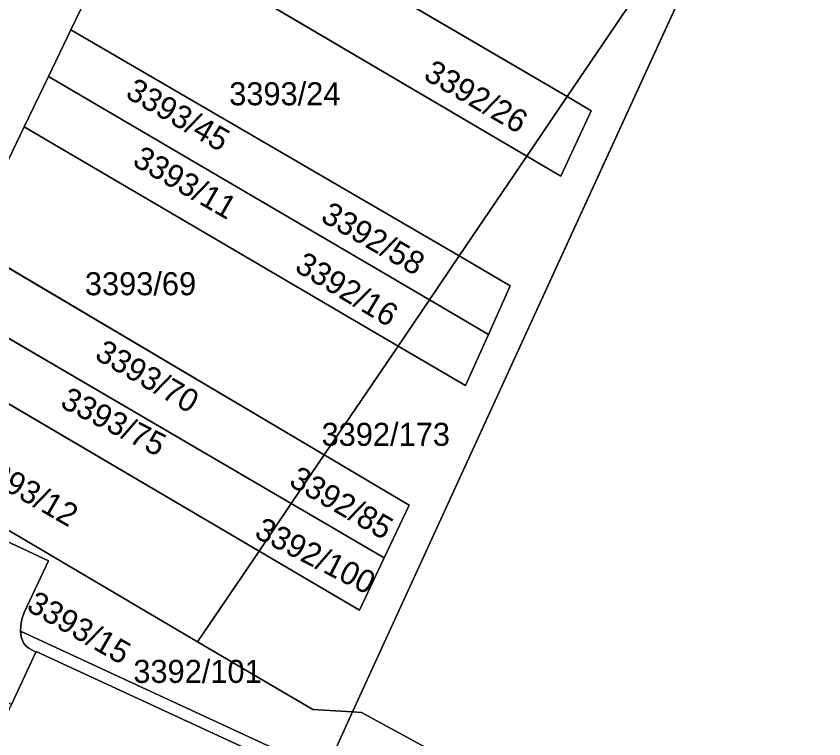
# Model space of a CAD drawing. Extents: x -262715 to -259381, y -1237238 to -1231182.
# Drawn here: x -261371.9 to -261301.7, y -1235929.8 to -1235867.1 of the extents above; entities that cross this region are included whole.
import ezdxf

# ---------------------------------------------------------------- set-up
doc = ezdxf.new("R2010")
doc.units = 0
for name, color, linetype in [('body_kn', 7, 'Continuous'), ('kladpar_druhypozemkov', 7, 'Continuous'), ('kladpar_hranice', 7, 'Continuous'), ('kladpar_parcelnecisla', 7, 'Continuous'), ('kladpar_plochy', 7, 'Continuous'), ('kladpar_sipky', 7, 'Continuous'), ('zuob_linie', 7, 'Continuous'), ('zuob_plochy', 7, 'Continuous')]:
    doc.layers.add(name, color=color, linetype=linetype)

msp = doc.modelspace()

# ---------------------------------------------------------------- linework, layer by layer
at = {"layer": 'body_kn'}
for p, q in [((-261367.16, -1235868.27), (-261367.16, -1235868.27)), ((-261367.16, -1235868.27), (-261367.16, -1235868.27)), ((-261369.1, -1235872.3), (-261369.1, -1235872.3)), ((-261369.1, -1235872.3), (-261369.1, -1235872.3)), ((-261324.01, -1235874.06), (-261324.01, -1235874.06)), ((-261324.01, -1235874.06), (-261324.01, -1235874.06)), ((-261321.93, -1235875.28), (-261321.93, -1235875.28)), ((-261371.21, -1235876.69), (-261371.21, -1235876.69)), ((-261371.21, -1235876.69), (-261371.21, -1235876.69)), ((-261327.53, -1235879.24), (-261327.53, -1235879.24)), ((-261327.53, -1235879.24), (-261327.53, -1235879.24)), ((-261324.58, -1235880.98), (-261324.58, -1235880.98)), ((-261333.4, -1235887.9), (-261333.4, -1235887.9)), ((-261333.4, -1235887.9), (-261333.4, -1235887.9)), ((-261328.96, -1235890.48), (-261328.96, -1235890.48)), ((-261335.99, -1235891.71), (-261335.99, -1235891.71)), ((-261335.99, -1235891.71), (-261335.99, -1235891.71)), ((-261330.85, -1235894.72), (-261330.85, -1235894.72)), ((-261330.85, -1235894.72), (-261330.85, -1235894.72)), ((-261338.71, -1235895.72), (-261338.71, -1235895.72)), ((-261338.71, -1235895.72), (-261338.71, -1235895.72)), ((-261332.86, -1235899.14), (-261332.86, -1235899.14)), ((-261332.86, -1235899.14), (-261332.86, -1235899.14)), ((-261345.13, -1235905.18), (-261345.13, -1235905.18)), ((-261345.13, -1235905.18), (-261345.13, -1235905.18)), ((-261348, -1235909.41), (-261348, -1235909.41)), ((-261337.75, -1235909.55), (-261337.75, -1235909.55)), ((-261350.79, -1235913.53), (-261350.79, -1235913.53)), ((-261350.79, -1235913.53), (-261350.79, -1235913.53)), ((-261369.08, -1235914.38), (-261369.08, -1235914.38)), ((-261339.93, -1235914.13), (-261339.93, -1235914.13)), ((-261339.93, -1235914.13), (-261339.93, -1235914.13)), ((-261342.06, -1235918.65), (-261342.06, -1235918.65)), ((-261371.41, -1235919.44), (-261371.41, -1235919.44)), ((-261371.21, -1235918.88), (-261371.21, -1235918.88)), ((-261371.49, -1235920.03), (-261371.49, -1235920.03)), ((-261371.51, -1235920.48), (-261371.51, -1235920.48)), ((-261371.45, -1235921.01), (-261371.45, -1235921.01)), ((-261371.22, -1235921.56), (-261371.22, -1235921.56)), ((-261356.13, -1235921.41), (-261356.13, -1235921.41)), ((-261356.13, -1235921.41), (-261356.13, -1235921.41)), ((-261371.03, -1235921.8), (-261371.03, -1235921.8)), ((-261370.81, -1235921.97), (-261370.81, -1235921.97)), ((-261370.19, -1235922.32), (-261370.19, -1235922.32)), ((-261370.16, -1235922.25), (-261370.16, -1235922.25)), ((-261346.13, -1235927.3), (-261346.13, -1235927.3)), ((-261342.66, -1235927.5), (-261342.66, -1235927.5)), ((-261342.66, -1235927.5), (-261342.66, -1235927.5)), ((-261341.89, -1235927.54), (-261341.89, -1235927.54)), ((-261341.89, -1235927.54), (-261341.89, -1235927.54))]:
    msp.add_line(p, q, dxfattribs=at)
at = {"layer": 'kladpar_druhypozemkov'}
for p, q in [((-261346.94, -1235872.59), (-261346.94, -1235872.59)), ((-261364.07, -1235873.52), (-261364.07, -1235873.52)), ((-261324.34, -1235877.36), (-261324.34, -1235877.36)), ((-261365.48, -1235878.07), (-261365.48, -1235878.07)), ((-261361.27, -1235889.66), (-261361.27, -1235889.66)), ((-261333.24, -1235892.93), (-261333.24, -1235892.93)), ((-261366.82, -1235896.06), (-261366.82, -1235896.06)), ((-261333.79, -1235898.01), (-261333.79, -1235898.01)), ((-261368.44, -1235900.45), (-261368.44, -1235900.45)), ((-261339.63, -1235902.21), (-261339.63, -1235902.21)), ((-261369.42, -1235907.68), (-261369.42, -1235907.68)), ((-261341.83, -1235909.49), (-261341.83, -1235909.49)), ((-261344.46, -1235913.47), (-261344.46, -1235913.47)), ((-261365.41, -1235919.57), (-261365.41, -1235919.57)), ((-261358.61, -1235927.02), (-261358.61, -1235927.02))]:
    msp.add_line(p, q, dxfattribs=at)
at = {"layer": 'kladpar_hranice'}
for p, q in [((-261305.98, -1235847.48), (-261342.66, -1235927.5)), ((-261324.01, -1235874.06), (-261305.98, -1235847.48)), ((-261360.53, -1235852.69), (-261324.01, -1235874.06)), ((-261324.01, -1235874.06), (-261360.53, -1235852.69)), ((-261362.88, -1235858.42), (-261327.53, -1235879.24)), ((-261369.1, -1235872.3), (-261367.16, -1235868.27)), ((-261333.4, -1235887.9), (-261367.16, -1235868.27)), ((-261367.16, -1235868.27), (-261333.4, -1235887.9)), ((-261371.21, -1235876.69), (-261369.1, -1235872.3)), ((-261335.99, -1235891.71), (-261369.1, -1235872.3)), ((-261369.1, -1235872.3), (-261335.99, -1235891.71)), ((-261327.53, -1235879.24), (-261324.01, -1235874.06)), ((-261376.11, -1235886.85), (-261371.21, -1235876.69)), ((-261338.71, -1235895.72), (-261371.21, -1235876.69)), ((-261371.21, -1235876.69), (-261338.71, -1235895.72)), ((-261327.53, -1235879.24), (-261333.4, -1235887.9)), ((-261333.4, -1235887.9), (-261327.53, -1235879.24)), ((-261376.11, -1235886.85), (-261345.13, -1235905.18)), ((-261333.4, -1235887.9), (-261335.99, -1235891.71)), ((-261348, -1235909.41), (-261378.39, -1235891.64)), ((-261378.39, -1235891.64), (-261348, -1235909.41)), ((-261335.99, -1235891.71), (-261338.71, -1235895.72)), ((-261350.79, -1235913.53), (-261380.48, -1235896.1)), ((-261380.48, -1235896.1), (-261350.79, -1235913.53)), ((-261345.13, -1235905.18), (-261348, -1235909.41)), ((-261348, -1235909.41), (-261345.13, -1235905.18)), ((-261348, -1235909.41), (-261350.79, -1235913.53)), ((-261350.79, -1235913.53), (-261348, -1235909.41)), ((-261348, -1235909.41), (-261339.93, -1235914.13)), ((-261350.79, -1235913.53), (-261356.13, -1235921.41)), ((-261356.13, -1235921.41), (-261350.79, -1235913.53)), ((-261342.66, -1235927.5), (-261341.89, -1235927.54))]:
    msp.add_line(p, q, dxfattribs=at)
for points in [[(-261319.46, -1235828.94), (-261311.13, -1235840.39), (-261305.98, -1235847.48), (-261324.01, -1235874.06)], [(-261386.5, -1236069.65), (-261377.1, -1236074.79), (-261372.8, -1236072.22), (-261361.27, -1236060.35), (-261345.62, -1236044.25), (-261341.5, -1236035.34), (-261337.33, -1236026.34), (-261329.78, -1236010.04), (-261326.26, -1236002.43), (-261322.63, -1235994.6), (-261319.1, -1235986.99), (-261315.58, -1235979.39), (-261312.39, -1235972.5), (-261308.86, -1235964.89), (-261301.71, -1235949.44), (-261323.71, -1235937.45), (-261341.89, -1235927.54), (-261342.66, -1235927.5), (-261305.98, -1235847.48)], [(-261367.16, -1235868.27), (-261365.45, -1235864.71), (-261362.88, -1235858.42)], [(-261324.01, -1235874.06), (-261327.53, -1235879.24), (-261362.88, -1235858.42)], [(-261365.45, -1235864.71), (-261367.16, -1235868.27), (-261369.1, -1235872.3), (-261371.21, -1235876.69), (-261376.11, -1235886.85)], [(-261324.01, -1235874.06), (-261321.93, -1235875.28), (-261324.58, -1235880.98), (-261327.53, -1235879.24)], [(-261327.53, -1235879.24), (-261324.58, -1235880.98), (-261321.93, -1235875.28), (-261324.01, -1235874.06)], [(-261338.71, -1235895.72), (-261345.13, -1235905.18), (-261376.11, -1235886.85)], [(-261330.85, -1235894.72), (-261335.99, -1235891.71), (-261333.4, -1235887.9)], [(-261333.4, -1235887.9), (-261328.96, -1235890.48), (-261330.85, -1235894.72)], [(-261330.85, -1235894.72), (-261328.96, -1235890.48), (-261333.4, -1235887.9)], [(-261332.86, -1235899.14), (-261338.71, -1235895.72), (-261335.99, -1235891.71), (-261330.85, -1235894.72), (-261332.86, -1235899.14)], [(-261338.71, -1235895.72), (-261332.86, -1235899.14), (-261330.85, -1235894.72)], [(-261350.79, -1235913.53), (-261342.06, -1235918.65), (-261339.93, -1235914.13), (-261337.75, -1235909.55), (-261345.13, -1235905.18), (-261338.71, -1235895.72)], [(-261356.13, -1235921.41), (-261378.64, -1235908.15), (-261384.51, -1235904.69)], [(-261345.13, -1235905.18), (-261337.75, -1235909.55), (-261339.93, -1235914.13), (-261348, -1235909.41)], [(-261379.31, -1235909.59), (-261378.64, -1235908.15), (-261356.13, -1235921.41)], [(-261389.65, -1235931.92), (-261386.57, -1235925.27), (-261384.63, -1235921.08), (-261382.66, -1235916.82), (-261380.59, -1235912.37), (-261379.31, -1235909.59), (-261369.08, -1235914.38), (-261371.21, -1235918.88), (-261371.41, -1235919.44), (-261371.49, -1235920.03), (-261371.51, -1235920.48), (-261371.45, -1235921.01), (-261371.22, -1235921.56), (-261371.03, -1235921.8), (-261370.81, -1235921.97), (-261370.19, -1235922.32), (-261372.29, -1235926.85), (-261373.19, -1235926.48), (-261373.83, -1235926.45), (-261374.48, -1235926.65), (-261375.29, -1235927.32), (-261387.89, -1235954.56)], [(-261342.66, -1235927.5), (-261345.06, -1235932.74), (-261371.51, -1235920.48), (-261371.49, -1235920.03), (-261371.41, -1235919.44), (-261371.21, -1235918.88), (-261369.08, -1235914.38), (-261379.31, -1235909.59)], [(-261339.93, -1235914.13), (-261342.06, -1235918.65), (-261350.79, -1235913.53)], [(-261345.49, -1235933.67), (-261370.16, -1235922.25), (-261370.19, -1235922.32), (-261370.81, -1235921.97), (-261371.03, -1235921.8), (-261371.22, -1235921.56), (-261371.45, -1235921.01), (-261371.51, -1235920.48), (-261345.06, -1235932.74), (-261345.49, -1235933.67)], [(-261342.66, -1235927.5), (-261346.13, -1235927.3), (-261356.13, -1235921.41)], [(-261356.13, -1235921.41), (-261346.13, -1235927.3), (-261342.66, -1235927.5)], [(-261385.72, -1235955.84), (-261372.29, -1235926.85), (-261370.19, -1235922.32), (-261370.16, -1235922.25), (-261345.49, -1235933.67), (-261367.6, -1235981.9), (-261374.62, -1235992.24), (-261397.64, -1235981.58), (-261397.56, -1235981.41), (-261396.6, -1235979.34), (-261394.51, -1235974.82)], [(-261338.02, -1235958.75), (-261329.38, -1235939.99), (-261345.06, -1235932.74), (-261342.66, -1235927.5)], [(-261341.89, -1235927.54), (-261323.71, -1235937.45), (-261330.9, -1235952.98), (-261334.46, -1235960.66), (-261338.02, -1235958.75)]]:
    msp.add_lwpolyline(points, dxfattribs=at)
at = {"layer": 'kladpar_plochy'}
for points in [[(-261358.1, -1235846.74), (-261355.45, -1235838.38), (-261345.16, -1235835.79), (-261326.35, -1235819.47), (-261325.36, -1235820.83), (-261336.23, -1235843.76), (-261333.68, -1235845.24), (-261331.14, -1235846.72), (-261328.6, -1235848.19), (-261319.46, -1235828.94), (-261311.13, -1235840.39), (-261305.98, -1235847.48), (-261324.01, -1235874.06), (-261360.53, -1235852.69)], [(-261342.66, -1235927.5), (-261346.13, -1235927.3), (-261356.13, -1235921.41), (-261350.79, -1235913.53), (-261342.06, -1235918.65), (-261339.93, -1235914.13), (-261337.75, -1235909.55), (-261345.13, -1235905.18), (-261338.71, -1235895.72), (-261332.86, -1235899.14), (-261330.85, -1235894.72), (-261328.96, -1235890.48), (-261333.4, -1235887.9), (-261327.53, -1235879.24), (-261324.58, -1235880.98), (-261321.93, -1235875.28), (-261324.01, -1235874.06), (-261305.98, -1235847.48)], [(-261362.88, -1235858.42), (-261360.53, -1235852.69), (-261324.01, -1235874.06), (-261327.53, -1235879.24)], [(-261327.53, -1235879.24), (-261333.4, -1235887.9), (-261367.16, -1235868.27), (-261365.45, -1235864.71), (-261362.88, -1235858.42)], [(-261367.16, -1235868.27), (-261333.4, -1235887.9), (-261335.99, -1235891.71), (-261369.1, -1235872.3)], [(-261371.21, -1235876.69), (-261369.1, -1235872.3), (-261335.99, -1235891.71), (-261338.71, -1235895.72)], [(-261324.01, -1235874.06), (-261321.93, -1235875.28), (-261324.58, -1235880.98), (-261327.53, -1235879.24)], [(-261376.11, -1235886.85), (-261371.21, -1235876.69), (-261338.71, -1235895.72), (-261345.13, -1235905.18)], [(-261376.11, -1235886.85), (-261345.13, -1235905.18), (-261348, -1235909.41), (-261378.39, -1235891.64), (-261377.66, -1235890.08)], [(-261333.4, -1235887.9), (-261328.96, -1235890.48), (-261330.85, -1235894.72), (-261335.99, -1235891.71)], [(-261350.79, -1235913.53), (-261380.48, -1235896.1), (-261378.39, -1235891.64), (-261348, -1235909.41)], [(-261332.86, -1235899.14), (-261338.71, -1235895.72), (-261335.99, -1235891.71), (-261330.85, -1235894.72)], [(-261380.48, -1235896.1), (-261350.79, -1235913.53), (-261356.13, -1235921.41), (-261378.64, -1235908.15), (-261384.51, -1235904.69)], [(-261345.13, -1235905.18), (-261337.75, -1235909.55), (-261339.93, -1235914.13), (-261348, -1235909.41)], [(-261356.13, -1235921.41), (-261346.13, -1235927.3), (-261342.66, -1235927.5), (-261345.06, -1235932.74), (-261371.51, -1235920.48), (-261371.49, -1235920.03), (-261371.41, -1235919.44), (-261371.21, -1235918.88), (-261369.08, -1235914.38), (-261379.31, -1235909.59), (-261378.64, -1235908.15)], [(-261339.93, -1235914.13), (-261342.06, -1235918.65), (-261350.79, -1235913.53), (-261348, -1235909.41)], [(-261345.49, -1235933.67), (-261370.16, -1235922.25), (-261370.19, -1235922.32), (-261370.81, -1235921.97), (-261371.03, -1235921.8), (-261371.22, -1235921.56), (-261371.45, -1235921.01), (-261371.51, -1235920.48), (-261345.06, -1235932.74)], [(-261365.58, -1235967.67), (-261381.27, -1235958.45), (-261385.72, -1235955.84), (-261372.29, -1235926.85), (-261370.19, -1235922.32), (-261370.16, -1235922.25), (-261345.49, -1235933.67), (-261367.6, -1235981.9), (-261374.62, -1235992.24), (-261397.64, -1235981.58), (-261397.56, -1235981.41), (-261396.6, -1235979.34), (-261394.51, -1235974.82), (-261392.97, -1235975.72), (-261374.7, -1235986.37), (-261373.56, -1235984.04), (-261391.5, -1235973.55), (-261393.4, -1235972.44), (-261387.89, -1235960.55), (-261384.17, -1235962.74), (-261367.87, -1235972.36)], [(-261341.89, -1235927.54), (-261323.71, -1235937.45), (-261330.9, -1235952.98), (-261334.46, -1235960.66), (-261338.02, -1235958.75), (-261329.38, -1235939.99), (-261345.06, -1235932.74), (-261342.66, -1235927.5)]]:
    msp.add_lwpolyline(points, close=True, dxfattribs=at)
for points in [[(-261345.62, -1236044.25), (-261341.5, -1236035.34), (-261337.33, -1236026.34), (-261329.78, -1236010.04), (-261326.26, -1236002.43), (-261322.63, -1235994.6), (-261319.1, -1235986.99), (-261315.58, -1235979.39), (-261312.39, -1235972.5), (-261308.86, -1235964.89), (-261301.71, -1235949.44), (-261323.71, -1235937.45), (-261341.89, -1235927.54), (-261342.66, -1235927.5), (-261305.98, -1235847.48)], [(-261365.45, -1235864.71), (-261367.16, -1235868.27), (-261369.1, -1235872.3), (-261371.21, -1235876.69), (-261376.11, -1235886.85)], [(-261379.31, -1235909.59), (-261369.08, -1235914.38), (-261371.21, -1235918.88), (-261371.41, -1235919.44), (-261371.49, -1235920.03), (-261371.51, -1235920.48), (-261371.45, -1235921.01), (-261371.22, -1235921.56), (-261371.03, -1235921.8), (-261370.81, -1235921.97), (-261370.19, -1235922.32), (-261372.29, -1235926.85)]]:
    msp.add_lwpolyline(points, dxfattribs=at)
at = {"layer": 'kladpar_sipky'}
for p, q in [((-261324.4, -1235879.04), (-261324.4, -1235879.04)), ((-261333.11, -1235890.26), (-261333.11, -1235890.26)), ((-261335.19, -1235893.7), (-261335.19, -1235893.7)), ((-261355.46, -1235928.56), (-261355.46, -1235928.56))]:
    msp.add_line(p, q, dxfattribs=at)
at = {"layer": 'zuob_linie'}
for points in [[(-261400, -1236050), (-261396.36, -1236041.07), (-261392.68, -1236032.07), (-261390.31, -1236026.25), (-261389.52, -1236024.31), (-261379.2, -1235999), (-261374.62, -1235992.24), (-261367.6, -1235981.9), (-261345.49, -1235933.67), (-261345.06, -1235932.74), (-261342.66, -1235927.5), (-261305.98, -1235847.48)], [(-261305.98, -1235847.48), (-261342.66, -1235927.5), (-261345.06, -1235932.74), (-261345.49, -1235933.67), (-261367.6, -1235981.9), (-261374.62, -1235992.24), (-261379.2, -1235999), (-261389.52, -1236024.31), (-261390.31, -1236026.25), (-261392.68, -1236032.07), (-261396.36, -1236041.07), (-261400, -1236050)]]:
    msp.add_lwpolyline(points, dxfattribs=at)
at = {"layer": 'zuob_plochy'}
for points in [[(-261400, -1236050), (-261396.36, -1236041.07), (-261392.68, -1236032.07), (-261390.31, -1236026.25), (-261389.52, -1236024.31), (-261379.2, -1235999), (-261374.62, -1235992.24), (-261367.6, -1235981.9), (-261345.49, -1235933.67), (-261345.06, -1235932.74), (-261342.66, -1235927.5), (-261305.98, -1235847.48)], [(-261305.98, -1235847.48), (-261342.66, -1235927.5), (-261345.06, -1235932.74), (-261345.49, -1235933.67), (-261367.6, -1235981.9), (-261374.62, -1235992.24), (-261379.2, -1235999), (-261389.52, -1236024.31), (-261390.31, -1236026.25), (-261392.68, -1236032.07), (-261396.36, -1236041.07), (-261400, -1236050)]]:
    msp.add_lwpolyline(points, dxfattribs=at)

# ---------------------------------------------------------------- texts
at = {"layer": 'kladpar_parcelnecisla'}
for s, rotation, p in [('3392/26', 330, (-261336.6, -1235872.487)), ('3393/45', 330, (-261362.506, -1235874.074)), ('3393/11', 330, (-261361.899, -1235879.961)), ('3392/58', 330, (-261345.543, -1235884.82)), ('3392/16', 329, (-261347.806, -1235889.142)), ('3393/70', 330, (-261365.175, -1235896.79)), ('3393/75', 333, (-261368.179, -1235900.978)), ('3393/12', 330, (-261375.669, -1235906.663)), ('3392/85', 330, (-261348.3, -1235907.777)), ('3392/100', 333, (-261351.301, -1235912.288)), ('3393/15', 330, (-261371.102, -1235918.619))]:
    msp.add_text(s, height=2, rotation=rotation, dxfattribs=at).set_placement(p)
for s, p in [('3393/24', (-261353.385, -1235874.81)), ('3393/69', (-261365.928, -1235891.31)), ('3392/173', (-261345.359, -1235904.39)), ('3392/101', (-261361.716, -1235924.98))]:
    msp.add_text(s, height=2, dxfattribs=at).set_placement(p)

doc.saveas('drawing.dxf')
